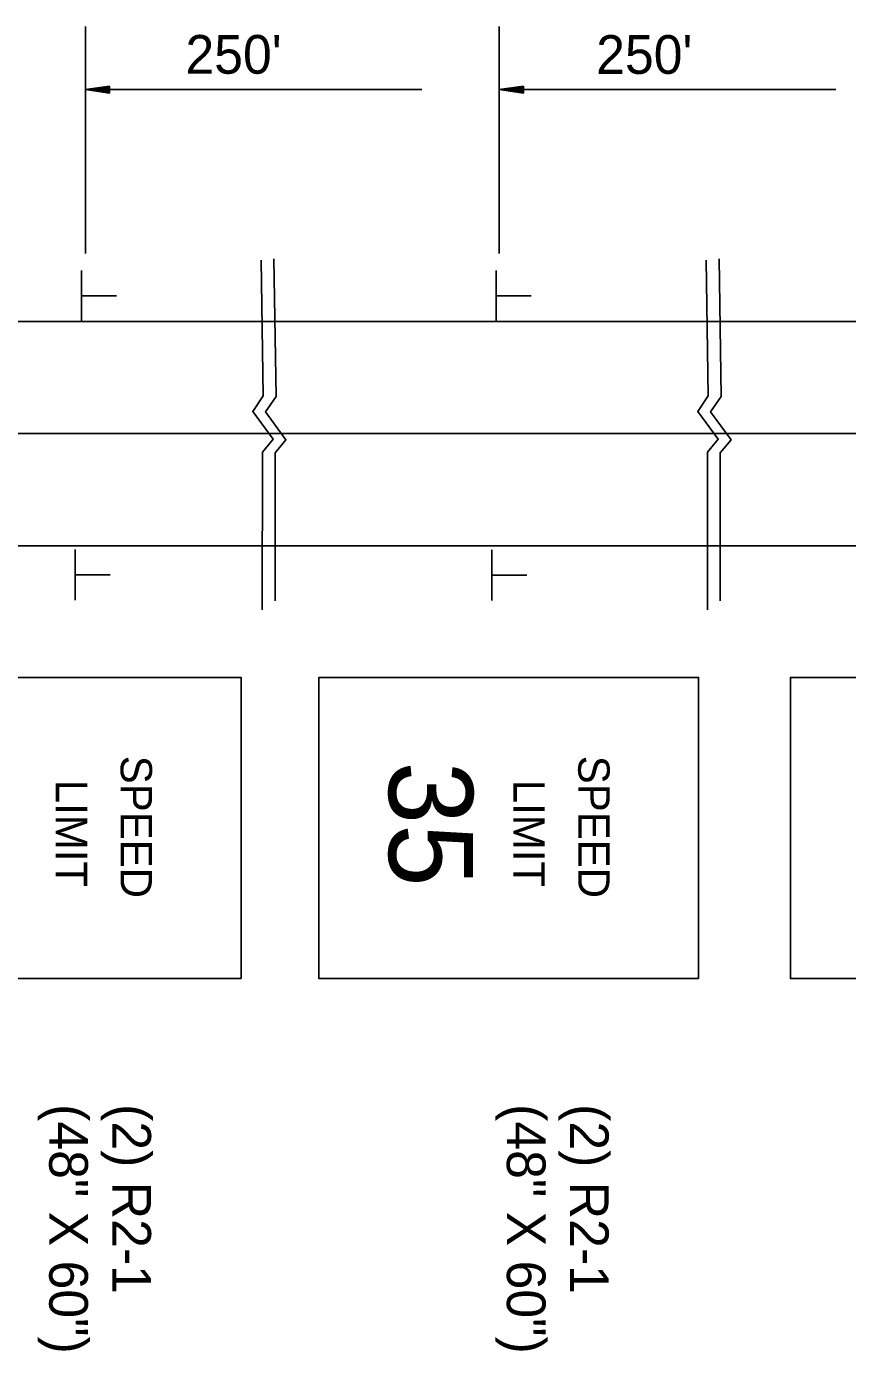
# Model space of a CAD drawing. Extents: x 1678017 to 1687792, y 404433 to 413488.
# Drawn here: x 1683749.5 to 1683876.8, y 411188.4 to 411393.7 of the extents above; entities that cross this region are included whole.
import ezdxf

# ---------------------------------------------------------------- set-up
doc = ezdxf.new("R2010")
doc.units = 0
doc.layers.add('Default', color=7, linetype='Continuous')

msp = doc.modelspace()

# ---------------------------------------------------------------- linework, layer by layer
at = {"layer": 'Default'}
for p, q in [((1683758.67, 411393.65), (1683758.67, 411358.44)), ((1683822.83, 411393.65), (1683822.83, 411358.44)), ((1683762.42, 411384.42), (1683758.67, 411383.86)), ((1683758.67, 411383.86), (1683810.86, 411383.86)), ((1683762.42, 411383.3), (1683758.67, 411383.86)), ((1683762.42, 411384.33), (1683759.29, 411383.86)), ((1683762.42, 411383.39), (1683759.29, 411383.86)), ((1683762.42, 411384.24), (1683759.94, 411383.86)), ((1683762.42, 411383.49), (1683759.94, 411383.86)), ((1683762.42, 411384.14), (1683760.56, 411383.86)), ((1683762.42, 411383.58), (1683760.56, 411383.86)), ((1683762.42, 411384.05), (1683761.2, 411383.86)), ((1683762.42, 411383.68), (1683761.2, 411383.86)), ((1683762.42, 411383.95), (1683761.82, 411383.86)), ((1683762.42, 411383.77), (1683761.82, 411383.86)), ((1683762.42, 411383.3), (1683762.42, 411384.42)), ((1683826.58, 411384.42), (1683822.83, 411383.86)), ((1683822.83, 411383.86), (1683875.02, 411383.86)), ((1683826.58, 411383.3), (1683822.83, 411383.86)), ((1683826.58, 411384.33), (1683823.45, 411383.86)), ((1683826.58, 411383.39), (1683823.45, 411383.86)), ((1683826.58, 411384.24), (1683824.1, 411383.86)), ((1683826.58, 411383.49), (1683824.1, 411383.86)), ((1683826.58, 411384.14), (1683824.72, 411383.86)), ((1683826.58, 411383.58), (1683824.72, 411383.86)), ((1683826.58, 411384.05), (1683825.36, 411383.86)), ((1683826.58, 411383.68), (1683825.36, 411383.86)), ((1683826.58, 411383.95), (1683825.99, 411383.86)), ((1683826.58, 411383.77), (1683825.99, 411383.86)), ((1683826.58, 411383.3), (1683826.58, 411384.42)), ((1683758.05, 411348.01), (1683758.05, 411355.83)), ((1683822.36, 411348.01), (1683822.36, 411355.83)), ((1683758.16, 411351.9), (1683763.5, 411351.9)), ((1683822.47, 411351.9), (1683827.81, 411351.9)), ((1683714.25, 411347.94), (1683780.87, 411347.94)), ((1683780.87, 411347.94), (1683849.88, 411347.94)), ((1683849.88, 411347.94), (1683923.82, 411347.94)), ((1683719.7, 411330.56), (1683780.87, 411330.56)), ((1683780.87, 411330.56), (1683849.88, 411330.56)), ((1683849.88, 411330.56), (1683924.27, 411330.56)), ((1683714.31, 411313.17), (1683780.87, 411313.17)), ((1683757.08, 411304.74), (1683757.08, 411312.57)), ((1683780.87, 411313.17), (1683849.88, 411313.17)), ((1683821.68, 411304.69), (1683821.68, 411312.51)), ((1683849.88, 411313.17), (1683924.73, 411313.17)), ((1683757.2, 411308.64), (1683762.54, 411308.64)), ((1683821.79, 411308.58), (1683827.13, 411308.58))]:
    msp.add_line(p, q, dxfattribs=at)
for points in [[(1683785.92, 411357.44), (1683786.24, 411336.41), (1683784.62, 411333.99), (1683787.78, 411329.66), (1683786.12, 411327.66), (1683786.11, 411303.21)], [(1683787.91, 411357.63), (1683788.24, 411336.32), (1683786.61, 411333.91), (1683789.78, 411329.58), (1683788.11, 411327.58), (1683788.11, 411304.61)], [(1683854.93, 411357.44), (1683855.25, 411336.41), (1683853.62, 411333.99), (1683856.79, 411329.66), (1683855.12, 411327.66), (1683855.11, 411303.21)], [(1683856.92, 411357.63), (1683857.24, 411336.32), (1683855.62, 411333.91), (1683858.78, 411329.58), (1683857.12, 411327.58), (1683857.11, 411304.61)]]:
    msp.add_lwpolyline(points, dxfattribs=at)
for points in [[(1683782.81, 411246.06), (1683723.94, 411246.06), (1683723.94, 411292.76), (1683782.81, 411292.76)], [(1683853.76, 411246.06), (1683794.89, 411246.06), (1683794.89, 411292.76), (1683853.76, 411292.76)], [(1683926.87, 411246.06), (1683868, 411246.06), (1683868, 411292.76), (1683926.87, 411292.76)]]:
    msp.add_lwpolyline(points, close=True, dxfattribs=at)

# ---------------------------------------------------------------- texts
for p in [(1683774.19, 411386.33), (1683837.87, 411386.31)]:
    msp.add_text("250'", height=6, dxfattribs=at).set_placement(p)
for s, height, p in [('SPEED', 4.865, (1683764.14, 411280.61)), ('35', 13.039, (1683805.74, 411279.71)), ('SPEED', 4.865, (1683835.09, 411280.61)), ('LIMIT', 4.865, (1683754.09, 411276.88)), ('LIMIT', 4.865, (1683825.04, 411276.88)), ('(48" X 60")', 6, (1683753.07, 411226.61)), ('(2) R2-1', 6, (1683762.85, 411226.61)), ('(48" X 60")', 6, (1683824.02, 411226.61)), ('(2) R2-1', 6, (1683833.8, 411226.61))]:
    msp.add_text(s, height=height, rotation=270, dxfattribs=at).set_placement(p)

doc.saveas('drawing.dxf')
